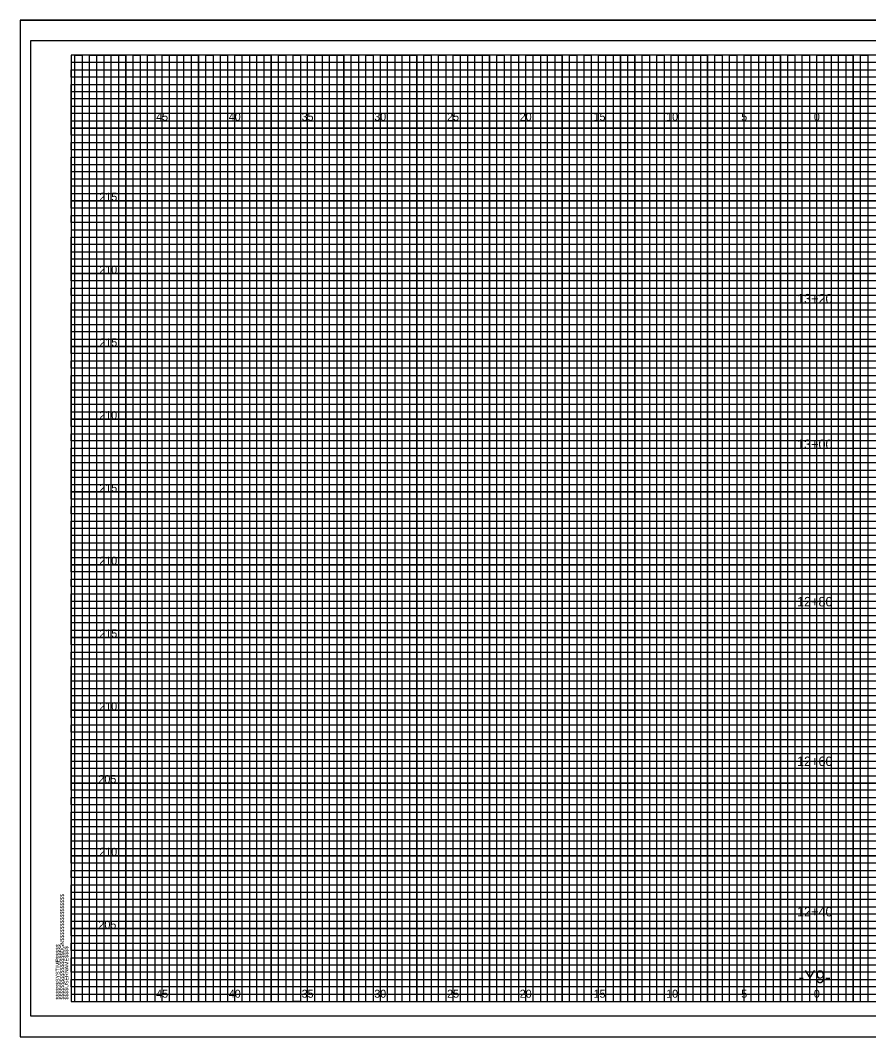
# Model space of a CAD drawing. Extents: x -4 to 103, y -2 to 492.
# Drawn here: x -3.5 to 54.8, y 139.2 to 209.1 of the extents above; entities that cross this region are included whole.
import ezdxf

# ---------------------------------------------------------------- set-up
doc = ezdxf.new("R2010")
doc.units = 0
for name, color, linetype in [('Old_Level_10', 7, 'Continuous'), ('Old_Level_16', 7, 'Continuous'), ('Old_Level_3', 7, 'Continuous'), ('Old_Level_5', 7, 'Continuous'), ('Old_Level_8', 7, 'Continuous'), ('Prop Dimension', 7, 'Continuous'), ('Prop Terminator CELL', 7, 'Continuous'), ('Prop XS Finish Grade', 7, 'Continuous'), ('Prop XS Finish Grade Earthwork', 7, 'Continuous'), ('Prop XS SE Text', 7, 'Continuous'), ('Prop XSC Text', 7, 'Continuous')]:
    doc.layers.add(name, color=color, linetype=linetype)

msp = doc.modelspace()

# ---------------------------------------------------------------- linework, layer by layer
at = {"layer": 'Old_Level_10'}
for p, q in [((1.25, 141.65), (1.25, 206.65)), ((3.75, 141.65), (3.75, 206.65)), ((6.25, 141.65), (6.25, 206.65)), ((8.75, 141.65), (8.75, 206.65)), ((11.25, 141.65), (11.25, 206.65)), ((13.75, 141.65), (13.75, 206.65)), ((16.25, 141.65), (16.25, 206.65)), ((18.75, 141.65), (18.75, 206.65)), ((21.25, 141.65), (21.25, 206.65)), ((23.75, 141.65), (23.75, 206.65)), ((26.25, 141.65), (26.25, 206.65)), ((28.75, 141.65), (28.75, 206.65)), ((31.25, 141.65), (31.25, 206.65)), ((33.75, 141.65), (33.75, 206.65)), ((36.25, 141.65), (36.25, 206.65)), ((38.75, 141.65), (38.75, 206.65)), ((41.25, 141.65), (41.25, 206.65)), ((43.75, 141.65), (43.75, 206.65)), ((46.25, 141.65), (46.25, 206.65)), ((48.75, 141.65), (48.75, 206.65)), ((51.25, 141.65), (51.25, 206.65)), ((53.75, 141.65), (53.75, 206.65)), ((0, 204.15), (74.25, 204.15)), ((0, 201.65), (102.5, 201.65)), ((0, 199.15), (102.5, 199.15)), ((0, 196.65), (102.5, 196.65)), ((0, 194.15), (102.5, 194.15)), ((0, 191.65), (102.5, 191.65)), ((0, 189.15), (102.5, 189.15)), ((0, 186.65), (102.5, 186.65)), ((0, 184.15), (102.5, 184.15)), ((0, 181.65), (102.5, 181.65)), ((0, 179.15), (102.5, 179.15)), ((0, 176.65), (102.5, 176.65)), ((0, 174.15), (102.5, 174.15)), ((0, 171.65), (102.5, 171.65)), ((0, 169.15), (102.5, 169.15)), ((0, 166.65), (102.5, 166.65)), ((0, 164.15), (102.5, 164.15)), ((0, 161.65), (102.5, 161.65)), ((0, 159.15), (102.5, 159.15)), ((0, 156.65), (102.5, 156.65)), ((0, 154.15), (102.5, 154.15)), ((0, 151.65), (102.5, 151.65)), ((0, 149.15), (102.5, 149.15)), ((0, 146.65), (102.5, 146.65)), ((0, 144.15), (102.5, 144.15))]:
    msp.add_line(p, q, dxfattribs=at)
at = {"layer": 'Old_Level_3'}
for p, q in [((-3.5, 209.05), (103.4, 209.05)), ((-3.5, 209.05), (-3.5, 139.225)), ((-3.5, 139.225), (103.4, 139.225))]:
    msp.add_line(p, q, dxfattribs=at)
at = {"layer": 'Old_Level_5'}
msp.add_lwpolyline([(103.4, 209.05), (-3.5, 209.05), (-3.5, 139.225), (103.4, 139.225)], close=True, dxfattribs=at)
at = {"layer": 'Old_Level_8'}
for points in [[(1.25, 141.65), (1.25, 206.65), (3.75, 206.65), (3.75, 141.65), (6.25, 141.65), (6.25, 206.65), (8.75, 206.65), (8.75, 141.65), (11.25, 141.65), (11.25, 206.65), (13.75, 206.65), (13.75, 141.65), (16.25, 141.65), (16.25, 206.65), (18.75, 206.65), (18.75, 141.65), (21.25, 141.65), (21.25, 206.65), (23.75, 206.65), (23.75, 141.65), (26.25, 141.65), (26.25, 206.65), (28.75, 206.65), (28.75, 141.65), (31.25, 141.65), (31.25, 206.65), (33.75, 206.65), (33.75, 141.65), (36.25, 141.65), (36.25, 206.65), (38.75, 206.65), (38.75, 141.65), (41.25, 141.65), (41.25, 206.65), (43.75, 206.65), (43.75, 141.65), (46.25, 141.65), (46.25, 206.65), (48.75, 206.65), (48.75, 141.65), (51.25, 141.65), (51.25, 206.65), (53.75, 206.65), (53.75, 141.65)], [(102.5, 201.65), (0, 201.65), (0, 204.15), (74.25, 204.15)], [(102.5, 196.65), (0, 196.65), (0, 199.15), (102.5, 199.15)], [(102.5, 191.65), (0, 191.65), (0, 194.15), (102.5, 194.15)], [(102.5, 186.65), (0, 186.65), (0, 189.15), (102.5, 189.15)], [(102.5, 181.65), (0, 181.65), (0, 184.15), (102.5, 184.15)], [(102.5, 176.65), (0, 176.65), (0, 179.15), (102.5, 179.15)], [(102.5, 171.65), (0, 171.65), (0, 174.15), (102.5, 174.15)], [(102.5, 166.65), (0, 166.65), (0, 169.15), (102.5, 169.15)], [(102.5, 161.65), (0, 161.65), (0, 164.15), (102.5, 164.15)], [(102.5, 156.65), (0, 156.65), (0, 159.15), (102.5, 159.15)], [(102.5, 151.65), (0, 151.65), (0, 154.15), (102.5, 154.15)], [(102.5, 146.65), (0, 146.65), (0, 149.15), (102.5, 149.15)], [(0, 144.15), (102.5, 144.15)]]:
    msp.add_lwpolyline(points, dxfattribs=at)
at = {"layer": 'Prop Dimension'}
for points in [[(0, 203.65), (0, 204.65), (74.25, 204.65), (74.25, 205.15), (0, 205.15), (0, 205.65), (74.25, 205.65), (74.25, 206.15), (0, 206.15)], [(0.25, 141.65), (0.25, 206.65), (0.75, 206.65), (0.75, 141.65), (1.75, 141.65), (1.75, 206.65), (2.25, 206.65), (2.25, 141.65), (2.75, 141.65), (2.75, 206.65), (3.25, 206.65), (3.25, 141.65), (4.25, 141.65), (4.25, 206.65), (4.75, 206.65), (4.75, 141.65), (5.25, 141.65), (5.25, 206.65), (5.75, 206.65), (5.75, 141.65), (6.75, 141.65), (6.75, 206.65), (7.25, 206.65), (7.25, 141.65), (7.75, 141.65), (7.75, 206.65), (8.25, 206.65), (8.25, 141.65), (9.25, 141.65), (9.25, 206.65), (9.75, 206.65), (9.75, 141.65), (10.25, 141.65), (10.25, 206.65), (10.75, 206.65), (10.75, 141.65), (11.75, 141.65), (11.75, 206.65), (12.25, 206.65), (12.25, 141.65), (12.75, 141.65), (12.75, 206.65), (13.25, 206.65), (13.25, 141.65), (14.25, 141.65), (14.25, 206.65), (14.75, 206.65), (14.75, 141.65), (15.75, 141.65), (15.25, 141.65), (15.25, 206.65), (15.75, 206.65), (15.75, 141.65), (16.75, 141.65), (16.75, 206.65), (17.25, 206.65), (17.25, 141.65), (17.75, 141.65), (17.75, 206.65), (18.25, 206.65), (18.25, 141.65), (19.25, 141.65), (19.25, 206.65), (19.75, 206.65), (19.75, 141.65), (20.25, 141.65), (20.25, 206.65), (20.75, 206.65), (20.75, 141.65), (21.75, 141.65), (21.75, 206.65), (22.25, 206.65), (22.25, 141.65), (22.75, 141.65), (22.75, 206.65), (23.25, 206.65), (23.25, 141.65), (24.25, 141.65), (24.25, 206.65), (24.75, 206.65), (24.75, 141.65), (25.25, 141.65), (25.25, 206.65), (25.75, 206.65), (25.75, 141.65), (26.75, 141.65), (26.75, 206.65), (27.25, 206.65), (27.25, 141.65), (27.75, 141.65), (27.75, 206.65), (28.25, 206.65), (28.25, 141.65), (29.25, 141.65), (29.25, 206.65), (29.75, 206.65), (29.75, 141.65), (30.25, 141.65), (30.25, 206.65), (30.75, 206.65), (30.75, 141.65)], [(30.75, 141.65), (31.75, 141.65), (31.75, 206.65), (32.25, 206.65), (32.25, 141.65), (32.75, 141.65), (32.75, 206.65), (33.25, 206.65), (33.25, 141.65), (34.25, 141.65), (34.25, 206.65), (34.75, 206.65), (34.75, 141.65), (35.25, 141.65), (35.25, 206.65), (35.75, 206.65), (35.75, 141.65), (36.75, 141.65), (36.75, 206.65), (37.25, 206.65), (37.25, 141.65), (37.75, 141.65), (37.75, 206.65), (37.75, 141.65)], [(38.25, 206.65), (38.25, 141.65), (39.25, 141.65), (39.25, 206.65), (39.75, 206.65), (39.75, 141.65), (40.25, 141.65), (40.25, 206.65), (40.75, 206.65), (40.75, 141.65), (41.75, 141.65), (41.75, 206.65), (42.25, 206.65), (42.25, 141.65), (42.75, 141.65), (42.75, 206.65), (43.25, 206.65), (43.25, 141.65), (43.75, 141.65), (44.25, 141.65), (44.25, 206.65), (44.75, 206.65), (44.75, 141.65), (45.25, 141.65), (45.25, 206.65), (45.75, 206.65), (45.75, 141.65), (46.75, 141.65), (46.75, 206.65), (47.25, 206.65), (47.25, 141.65), (47.75, 141.65), (47.75, 206.65), (48.25, 206.65), (48.25, 141.65), (49.25, 141.65), (49.25, 206.65), (49.75, 206.65), (49.75, 141.65), (50.25, 141.65), (50.25, 206.65), (50.75, 206.65), (50.75, 141.65), (51.75, 141.65), (51.75, 206.65), (52.25, 206.65), (52.25, 141.65), (52.75, 141.65), (52.75, 206.65), (53.25, 206.65), (53.25, 141.65), (54.25, 141.65), (54.25, 206.65), (54.75, 206.65), (54.75, 141.65), (55.25, 141.65)], [(102.5, 203.65), (0, 203.65)], [(102.5, 202.65), (0, 202.65), (0, 203.15), (102.5, 203.15)], [(102.5, 201.15), (0, 201.15), (0, 202.15), (102.5, 202.15)], [(102.5, 200.15), (0, 200.15), (0, 200.65), (102.5, 200.65)], [(102.5, 198.65), (0, 198.65), (0, 199.65), (102.5, 199.65)], [(102.5, 197.65), (0, 197.65), (0, 198.15), (102.5, 198.15)], [(102.5, 196.15), (0, 196.15), (0, 197.15), (102.5, 197.15)], [(102.5, 195.15), (0, 195.15), (0, 195.65), (102.5, 195.65)], [(0, 194.65), (102.5, 194.65)], [(102.5, 193.65), (0, 193.65)], [(102.5, 192.65), (0, 192.65), (0, 193.15), (102.5, 193.15)], [(102.5, 191.15), (0, 191.15), (0, 192.15), (102.5, 192.15)], [(102.5, 190.15), (0, 190.15), (0, 190.65), (102.5, 190.65)], [(102.5, 188.65), (0, 188.65), (0, 189.65), (102.5, 189.65)], [(102.5, 187.65), (0, 187.65), (0, 188.15), (102.5, 188.15)], [(102.5, 186.15), (0, 186.15), (0, 187.15), (102.5, 187.15)], [(102.5, 185.15), (0, 185.15), (0, 185.65), (102.5, 185.65)], [(102.5, 183.65), (0, 183.65), (0, 184.65), (102.5, 184.65)], [(102.5, 182.65), (0, 182.65), (0, 183.15), (102.5, 183.15)], [(102.5, 181.15), (0, 181.15), (0, 182.15), (102.5, 182.15)], [(102.5, 180.15), (0, 180.15), (0, 180.65), (102.5, 180.65)], [(102.5, 178.65), (0, 178.65), (0, 179.65), (102.5, 179.65)], [(102.5, 177.65), (0, 177.65), (0, 178.15), (102.5, 178.15)], [(102.5, 176.15), (0, 176.15), (0, 177.15), (102.5, 177.15)], [(102.5, 175.15), (0, 175.15), (0, 175.65), (102.5, 175.65)], [(102.5, 173.65), (0, 173.65), (0, 174.65), (102.5, 174.65)], [(102.5, 172.65), (0, 172.65), (0, 173.15)], [(0, 173.15), (102.5, 173.15)], [(102.5, 171.15), (0, 171.15), (0, 172.15), (102.5, 172.15)], [(102.5, 170.15), (0, 170.15), (0, 170.65), (102.5, 170.65)], [(102.5, 168.65), (0, 168.65), (0, 169.65), (102.5, 169.65)], [(102.5, 167.65), (0, 167.65), (0, 168.15), (102.5, 168.15)], [(102.5, 166.15), (0, 166.15), (0, 167.15), (102.5, 167.15)], [(102.5, 165.15), (0, 165.15), (0, 165.65), (102.5, 165.65)], [(102.5, 163.65), (0, 163.65), (0, 164.65), (102.5, 164.65)], [(102.5, 162.65), (0, 162.65), (0, 163.15), (102.5, 163.15)], [(102.5, 161.15), (0, 161.15), (0, 162.15), (102.5, 162.15)], [(102.5, 160.15), (0, 160.15), (0, 160.65), (102.5, 160.65)], [(102.5, 158.65), (0, 158.65), (0, 159.65), (102.5, 159.65)], [(102.5, 157.65), (0, 157.65), (0, 158.15), (102.5, 158.15)], [(102.5, 156.15), (0, 156.15), (0, 157.15), (102.5, 157.15)], [(102.5, 155.15), (0, 155.15), (0, 155.65), (102.5, 155.65)], [(102.5, 153.65), (0, 153.65), (0, 154.65), (102.5, 154.65)], [(102.5, 152.65), (0, 152.65), (0, 153.15), (102.5, 153.15)], [(102.5, 151.15), (0, 151.15), (0, 152.15), (102.5, 152.15)], [(102.5, 150.15), (0, 150.15), (0, 150.65), (102.5, 150.65)], [(102.5, 148.65), (0, 148.65), (0, 149.65), (102.5, 149.65)], [(102.5, 147.65), (0, 147.65), (0, 148.15), (102.5, 148.15)], [(102.5, 146.15), (0, 146.15), (0, 147.15), (102.5, 147.15)], [(102.5, 145.15), (0, 145.15), (0, 145.65), (102.5, 145.65)], [(102.5, 143.65), (0, 143.65), (0, 144.65), (102.5, 144.65)], [(102.5, 142.65), (0, 142.65), (0, 143.15), (102.5, 143.15)], [(0, 142.15), (102.5, 142.15)]]:
    msp.add_lwpolyline(points, dxfattribs=at)
at = {"layer": 'Prop XS SE Text'}
msp.add_lwpolyline([(103, 207.65), (-2.8, 207.65), (-2.8, 140.65), (103, 140.65)], close=True, dxfattribs=at)
at = {"layer": 'Prop XSC Text'}
msp.add_lwpolyline([(102.5, 206.65), (0, 206.65), (0, 141.65), (102.5, 141.65)], close=True, dxfattribs=at)

# ---------------------------------------------------------------- texts
at = {"layer": 'Old_Level_16'}
for s, p in [('45', (5.8399, 202.15)), ('40', (10.8313, 202.15)), ('35', (15.8399, 202.15)), ('30', (20.8313, 202.15)), ('25', (25.8399, 202.15)), ('20', (30.8313, 202.15)), ('15', (35.9058, 202.15)), ('10', (40.8971, 202.15)), ('5', (46.0574, 202.15)), ('0', (51.0488, 202.15)), ('0', (51.0488, 202.15)), ('45', (5.8399, 141.9)), ('40', (10.8313, 141.9)), ('35', (15.8399, 141.9)), ('30', (20.8313, 141.9)), ('25', (25.8399, 141.9)), ('20', (30.8313, 141.9)), ('15', (35.9058, 141.9)), ('10', (40.8971, 141.9)), ('5', (46.0574, 141.9)), ('0', (51.0488, 141.9)), ('0', (51.0488, 141.9))]:
    msp.add_text(s, height=0.55, dxfattribs=at).set_placement(p)
at = {"layer": 'Old_Level_8'}
msp.add_text('040397', height=0.0025, rotation=90, dxfattribs=at).set_placement((-0.0007, 206.6364))
at = {"layer": 'Prop Terminator CELL'}
msp.add_text('-Y9-', height=0.875, dxfattribs=at).set_placement((49.9985, 142.9))
at = {"layer": 'Prop XS Finish Grade'}
for s, p in [('13+20', (49.8934, 189.6004)), ('13+00', (49.8934, 179.596)), ('12+80', (49.8934, 168.7862)), ('12+60', (49.8934, 157.8177)), ('12+40', (49.8934, 147.4875))]:
    msp.add_text(s, height=0.65, dxfattribs=at).set_placement(p)
at = {"layer": 'Prop XS Finish Grade Earthwork'}
for s, p in [('215', (1.9383, 196.65)), ('210', (1.9296, 191.65)), ('215', (1.9383, 186.65)), ('210', (1.9296, 181.65)), ('215', (1.9383, 176.65)), ('210', (1.9296, 171.65)), ('215', (1.9383, 166.65)), ('210', (1.9296, 161.65)), ('205', (1.8724, 156.65)), ('210', (1.9296, 151.65)), ('205', (1.8724, 146.65))]:
    msp.add_text(s, height=0.55, dxfattribs=at).set_placement(p)
at = {"layer": 'Prop XSC Text'}
for s, p in [('$$$$$$$$$$$$$$$$DGN$$$$$$$$$$$$$$$$', (-0.5, 141.775)), ('$$$$$$SYSTIME$$$$$', (-0.7973, 141.7747)), ('$$$$USERNAME$$$$', (-0.2, 141.775))]:
    msp.add_text(s, height=0.2625, rotation=90, dxfattribs=at).set_placement(p)

doc.saveas('drawing.dxf')
